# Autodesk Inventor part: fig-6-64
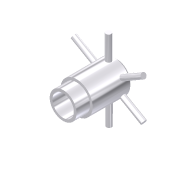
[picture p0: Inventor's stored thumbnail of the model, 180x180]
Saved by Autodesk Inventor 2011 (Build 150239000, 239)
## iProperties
Shininess: 77.0
Angle Display Precision: 2
Document Length Units: 11269
Document Angle Units: 11279
Document Time Units: 11290
Document Mass Units: 11283
Document Length Units Precision: 3
Document Angle Units Precision: 2
Compacted: True
Created: 2001-12
Part Number: fig-6-64
Document SubType Name: Modeling
Designer: Renu Muthoo
Density: 1 g/cm^3
Density: 0.0
Volumn: 0.0
Area: 0.0
PropertySet Name: Model Information
Control State: 0
Master: False
Checked Out: False
Author: Renu Muthoo
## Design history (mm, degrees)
sketch "Sketch2"
  geometry: L1 (-9.573, -4.327)-(-9.573, -5.327); L2 (-9.573, -5.327)-(-4.573, -5.327); L3 (-4.573, -5.327)-(-4.573, -6.327); L4 (-4.573, -6.327)-(9.427, -6.327); L5 (9.427, -6.327)-(10.427, -5.327); L6 (10.427, -5.327)-(10.427, -4.327); L7 (10.427, -4.327)-(-9.573, -4.327); L8 (-13.687, -0.327)-(14, -0.327)
  constraints: 16 end point, 5 parallel, 1 perpendicular, 1 vertical
  dimensions: "d9" = 20 distance of L6.end L1.start; "d10" = 5 distance of L1.end L2.end; "d11" = 12 diameter of L4 L8; "d12" = 10 diameter of L2 L8; "d13" = 8 diameter of L7 L8; "d14" = 45 deg angle of L5 L4; "d15" = 1 horizontal distance of L5.end L4.end
revolve "Revolution2" sketch "Sketch2" stored, may be unused: angle "d16" = 90 deg
workplane "Work Plane1"
workplane "Work Plane2"
sketch "Sketch3"
  geometry: L1 (-4, 8)-(4, 8) reference; C1 r 1 at (-0.098, 5)
  constraints: 1 centre point
  dimensions: "d18" = 3 distance from line of L1 C1.centre; "d19" = 2 diameter of C1
extrude "Extrusion1" join sketch "Sketch3" distance "d20" = 10; taper "d21" = 0 deg
pattern_circular "Circular Pattern3" dims angle "d29" = 360 deg
body "Solid1"
other parameters: "d17" = -1
